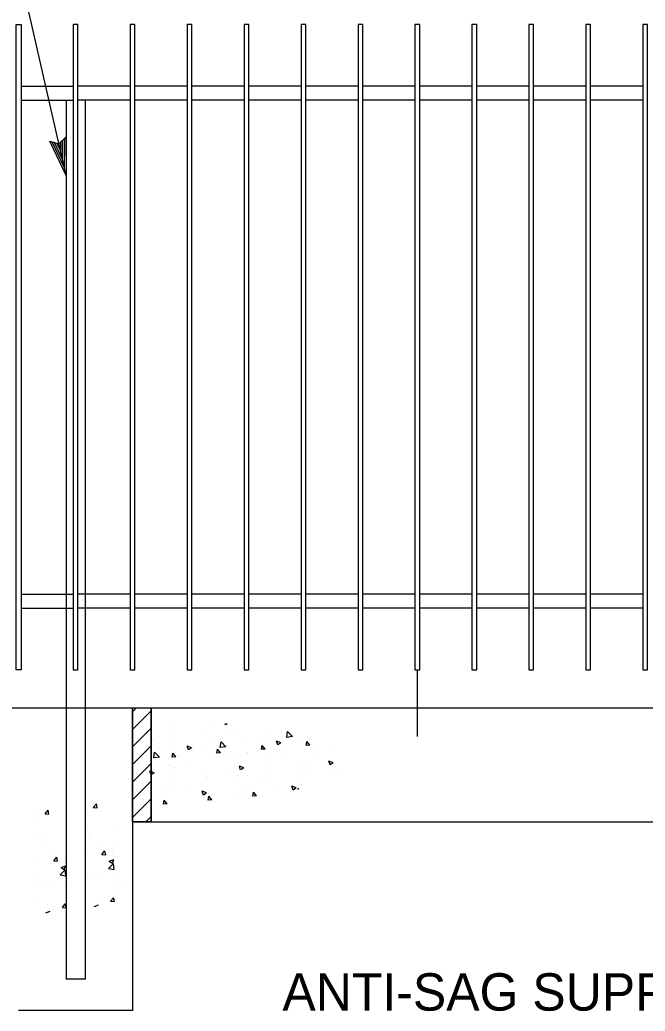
# Model space of a CAD drawing. Extents: x 6710407 to 6714861, y 1868090 to 1871317.
# Drawn here: x 6711630.5 to 6711730.9, y 1869739.6 to 1869898.7 of the extents above; entities that cross this region are included whole.
import ezdxf

# ---------------------------------------------------------------- set-up
doc = ezdxf.new("R2010")
doc.units = 0
for name, color, linetype in [('Erosion C (Lv35)', 7, 'Continuous'), ('G-MARK', 7, 'Continuous'), ('G-TEXT', 7, 'Continuous'), ('Nongeo Data(60)', 7, 'Continuous')]:
    doc.layers.add(name, color=color, linetype=linetype)

# ---------------------------------------------------------------- blocks, each defined once
blk = doc.blocks.new('SC8415')
at = {"layer": 'Erosion C (Lv35)'}
for p, q in [((-1.69662, 1.7688), (-1.69662, 1.7688)), ((-1.69606, 1.76963), (-1.69579, 1.76945)), ((-1.69579, 1.76945), (-1.69573, 1.76963)), ((-1.69408, 1.76913), (-1.69408, 1.76913)), ((-1.68715, 1.76926), (-1.68715, 1.76926)), ((-1.70943, 1.76711), (-1.70943, 1.76711)), ((-1.70689, 1.76745), (-1.70689, 1.76745)), ((-1.70669, 1.76754), (-1.7059, 1.76836)), ((-1.70669, 1.76754), (-1.70579, 1.7674)), ((-1.70579, 1.7674), (-1.7059, 1.76836)), ((-1.70304, 1.76795), (-1.70304, 1.76795)), ((-1.70278, 1.76714), (-1.70278, 1.76714)), ((-1.6975, 1.7679), (-1.6975, 1.7679)), ((-1.69309, 1.7676), (-1.69309, 1.7676)), ((-1.69228, 1.76861), (-1.69228, 1.76861)), ((-1.68716, 1.76862), (-1.68716, 1.76862)), ((-1.71312, 1.76577), (-1.71312, 1.76577)), ((-1.70955, 1.76614), (-1.70906, 1.76672)), ((-1.70955, 1.76614), (-1.70894, 1.76608)), ((-1.70894, 1.76609), (-1.70906, 1.76672)), ((-1.70791, 1.76649), (-1.70791, 1.76649)), ((-1.70672, 1.76656), (-1.70672, 1.76656)), ((-1.70494, 1.76557), (-1.70494, 1.76557)), ((-1.70484, 1.76651), (-1.70412, 1.76679)), ((-1.70484, 1.76651), (-1.70433, 1.76617)), ((-1.70433, 1.76617), (-1.70412, 1.76679)), ((-1.70226, 1.7655), (-1.70177, 1.76608)), ((-1.70226, 1.7655), (-1.70165, 1.76545)), ((-1.70165, 1.76545), (-1.70177, 1.76609)), ((-1.7013, 1.76633), (-1.7013, 1.76633)), ((-1.69901, 1.76659), (-1.69901, 1.76659)), ((-1.69588, 1.7661), (-1.69588, 1.7661)), ((-1.69585, 1.76586), (-1.69506, 1.76668)), ((-1.69585, 1.76586), (-1.69494, 1.76572)), ((-1.69494, 1.76572), (-1.69506, 1.76668)), ((-1.6929, 1.76563), (-1.6929, 1.76563)), ((-1.69045, 1.76587), (-1.69045, 1.76587)), ((-1.69023, 1.7657), (-1.68952, 1.76597)), ((-1.69023, 1.7657), (-1.68973, 1.76536)), ((-1.68973, 1.76536), (-1.68952, 1.76597)), ((-1.68727, 1.76588), (-1.68727, 1.76588)), ((-1.68649, 1.76648), (-1.68649, 1.76648)), ((-1.68503, 1.76565), (-1.68503, 1.76565)), ((-1.68473, 1.76639), (-1.68473, 1.76639)), ((-1.68394, 1.76681), (-1.68394, 1.76681)), ((-1.682, 1.76664), (-1.682, 1.76664)), ((-1.71086, 1.76455), (-1.71086, 1.76455)), ((-1.71, 1.76543), (-1.71, 1.76543)), ((-1.70571, 1.76395), (-1.70571, 1.76395)), ((-1.70458, 1.7652), (-1.70458, 1.7652)), ((-1.6993, 1.76479), (-1.6993, 1.76479)), ((-1.69916, 1.76497), (-1.69916, 1.76497)), ((-1.69762, 1.76452), (-1.69762, 1.76452)), ((-1.69675, 1.76513), (-1.69675, 1.76513)), ((-1.69658, 1.76435), (-1.69658, 1.76435)), ((-1.69497, 1.76486), (-1.69449, 1.76545)), ((-1.69497, 1.76486), (-1.69437, 1.76481)), ((-1.69437, 1.76481), (-1.69448, 1.76545)), ((-1.69373, 1.76474), (-1.69373, 1.76474)), ((-1.69241, 1.76523), (-1.69241, 1.76523)), ((-1.69065, 1.76537), (-1.69065, 1.76537)), ((-1.68831, 1.76451), (-1.68831, 1.76451)), ((-1.68769, 1.76423), (-1.6872, 1.76481)), ((-1.68769, 1.76423), (-1.68708, 1.76417)), ((-1.68708, 1.76417), (-1.6872, 1.76481)), ((-1.685, 1.76418), (-1.68421, 1.765)), ((-1.685, 1.76418), (-1.6841, 1.76404)), ((-1.6841, 1.76404), (-1.68421, 1.765)), ((-1.68289, 1.76428), (-1.68289, 1.76428)), ((-1.71337, 1.76324), (-1.71266, 1.76351)), ((-1.71337, 1.76324), (-1.71287, 1.7629)), ((-1.71325, 1.76239), (-1.71325, 1.76239)), ((-1.71287, 1.7629), (-1.71266, 1.76351)), ((-1.7121, 1.7631), (-1.7121, 1.7631)), ((-1.70956, 1.76344), (-1.70956, 1.76344)), ((-1.70843, 1.76232), (-1.70843, 1.76232)), ((-1.70803, 1.7631), (-1.70803, 1.7631)), ((-1.7029, 1.76375), (-1.7029, 1.76375)), ((-1.7025, 1.76334), (-1.7025, 1.76334)), ((-1.69877, 1.76242), (-1.69806, 1.7627)), ((-1.69877, 1.76242), (-1.69827, 1.76208)), ((-1.69826, 1.76208), (-1.69806, 1.7627)), ((-1.68916, 1.76247), (-1.68916, 1.76247)), ((-1.6874, 1.7625), (-1.6874, 1.7625)), ((-1.68662, 1.7628), (-1.68662, 1.7628)), ((-1.68277, 1.76331), (-1.68277, 1.76331)), ((-1.71417, 1.76163), (-1.71417, 1.76163)), ((-1.70874, 1.7614), (-1.70874, 1.7614)), ((-1.70332, 1.76117), (-1.70332, 1.76117)), ((-1.70197, 1.76078), (-1.70197, 1.76078)), ((-1.69943, 1.76112), (-1.69943, 1.76112)), ((-1.6979, 1.76094), (-1.6979, 1.76094)), ((-1.69775, 1.76113), (-1.69775, 1.76113)), ((-1.69558, 1.76162), (-1.69558, 1.76162)), ((-1.6927, 1.7608), (-1.6927, 1.7608)), ((-1.69253, 1.76185), (-1.69253, 1.76185)), ((-1.69247, 1.76071), (-1.69247, 1.76071)), ((-1.68677, 1.76182), (-1.68677, 1.76182)), ((-1.68417, 1.76161), (-1.68346, 1.76188)), ((-1.68417, 1.76161), (-1.68366, 1.76127)), ((-1.68366, 1.76127), (-1.68346, 1.76188)), ((-1.70839, 1.75994), (-1.70839, 1.75994)), ((-1.70815, 1.75972), (-1.70815, 1.75972)), ((-1.70775, 1.75896), (-1.70765, 1.75908)), ((-1.70762, 1.7589), (-1.70765, 1.75908)), ((-1.70731, 1.75915), (-1.7066, 1.75942)), ((-1.70731, 1.75915), (-1.7068, 1.75881)), ((-1.7068, 1.75881), (-1.7066, 1.75942)), ((-1.70302, 1.76037), (-1.70302, 1.76037)), ((-1.69862, 1.75978), (-1.69862, 1.75978)), ((-1.68752, 1.75912), (-1.68752, 1.75912)), ((-1.68705, 1.76048), (-1.68705, 1.76048)), ((-1.68544, 1.7593), (-1.68544, 1.7593)), ((-1.68224, 1.75988), (-1.68224, 1.75988)), ((-1.70455, 1.75876), (-1.70455, 1.75876)), ((-1.70085, 1.75786), (-1.70036, 1.75844)), ((-1.70085, 1.75786), (-1.70025, 1.7578)), ((-1.70024, 1.75781), (-1.70036, 1.75844)), ((-1.69825, 1.75762), (-1.69825, 1.75762)), ((-1.69787, 1.75775), (-1.69787, 1.75775)), ((-1.69357, 1.75722), (-1.69308, 1.7578)), ((-1.69296, 1.75717), (-1.69307, 1.75781)), ((-1.69271, 1.75833), (-1.692, 1.75861)), ((-1.69271, 1.75833), (-1.6922, 1.75799)), ((-1.69265, 1.75847), (-1.69265, 1.75847)), ((-1.6922, 1.75799), (-1.69199, 1.75861)), ((-1.69183, 1.75846), (-1.69183, 1.75846)), ((-1.68929, 1.7588), (-1.68929, 1.7588)), ((-1.69357, 1.75722), (-1.69296, 1.75717)), ((-1.68628, 1.75658), (-1.68579, 1.75717)), ((-1.68628, 1.75658), (-1.68567, 1.75653)), ((-1.68567, 1.75653), (-1.68579, 1.75717))]:
    blk.add_line(p, q, dxfattribs=at)

msp = doc.modelspace()

# ---------------------------------------------------------------- linework, layer by layer
at = {"layer": 'G-MARK'}
msp.add_lwpolyline([(6711637.97, 1869873.68), (6711620.12, 1869951.83), (6711630.31, 1869951.98)], dxfattribs=at)
at = {"layer": 'G-TEXT'}
for p, q in [((6711637.97, 1869873.68), (6711635.34, 1869879.23)), ((6711635.34, 1869879.23), (6711635.34, 1869879.23)), ((6711635.34, 1869879.23), (6711636.82, 1869878.75)), ((6711636.82, 1869878.75), (6711637.94, 1869879.83)), ((6711637.35, 1869879.23), (6711637.36, 1869876.37)), ((6711637.65, 1869879.54), (6711637.67, 1869875.02)), ((6711637.94, 1869879.83), (6711637.94, 1869879.83)), ((6711637.94, 1869879.83), (6711637.97, 1869873.68)), ((6711637.66, 1869875.03), (6711635.74, 1869879.08)), ((6711637.36, 1869876.37), (6711636.12, 1869878.99)), ((6711637.05, 1869877.72), (6711636.52, 1869878.84)), ((6711637.05, 1869878.98), (6711637.05, 1869877.72)), ((6711637.97, 1869873.68), (6711637.97, 1869873.68))]:
    msp.add_line(p, q, dxfattribs=at)
at = {"layer": 'Nongeo Data(60)'}
for p, q in [((6711639.5, 1869897.95), (6711639.5, 1869897.95)), ((6711630.74, 1869888.05), (6711639.12, 1869888.05)), ((6711648.26, 1869888.05), (6711639.88, 1869888.05)), ((6711657.41, 1869888.05), (6711649.02, 1869888.05)), ((6711666.55, 1869888.05), (6711658.17, 1869888.05)), ((6711675.69, 1869888.05), (6711667.31, 1869888.05)), ((6711684.84, 1869888.05), (6711676.46, 1869888.05)), ((6711693.98, 1869888.05), (6711685.6, 1869888.05)), ((6711703.13, 1869888.05), (6711694.74, 1869888.05)), ((6711712.27, 1869888.05), (6711703.89, 1869888.05)), ((6711721.41, 1869888.05), (6711713.03, 1869888.05)), ((6711730.56, 1869888.05), (6711722.18, 1869888.05)), ((6711630.74, 1869885.76), (6711639.12, 1869885.76)), ((6711637.97, 1869885.76), (6711637.97, 1869744.69)), ((6711648.26, 1869885.76), (6711639.88, 1869885.76)), ((6711641.02, 1869885.76), (6711641.02, 1869744.69)), ((6711657.41, 1869885.76), (6711649.02, 1869885.76)), ((6711666.55, 1869885.76), (6711658.17, 1869885.76)), ((6711675.69, 1869885.76), (6711667.31, 1869885.76)), ((6711684.84, 1869885.76), (6711676.46, 1869885.76)), ((6711693.98, 1869885.76), (6711685.6, 1869885.76)), ((6711703.13, 1869885.76), (6711694.74, 1869885.76)), ((6711712.27, 1869885.76), (6711703.89, 1869885.76)), ((6711721.41, 1869885.76), (6711713.03, 1869885.76)), ((6711730.56, 1869885.76), (6711722.18, 1869885.76)), ((6711630.74, 1869806.51), (6711639.12, 1869806.51)), ((6711648.26, 1869806.51), (6711639.88, 1869806.51)), ((6711657.41, 1869806.51), (6711649.02, 1869806.51)), ((6711666.55, 1869806.51), (6711658.17, 1869806.51)), ((6711675.69, 1869806.51), (6711667.31, 1869806.51)), ((6711684.84, 1869806.51), (6711676.46, 1869806.51)), ((6711693.98, 1869806.51), (6711685.6, 1869806.51)), ((6711703.13, 1869806.51), (6711694.74, 1869806.51)), ((6711712.27, 1869806.51), (6711703.89, 1869806.51)), ((6711721.41, 1869806.51), (6711713.03, 1869806.51)), ((6711730.56, 1869806.51), (6711722.18, 1869806.51)), ((6711630.74, 1869804.23), (6711639.12, 1869804.23)), ((6711648.26, 1869804.23), (6711639.88, 1869804.23)), ((6711657.41, 1869804.23), (6711649.02, 1869804.23)), ((6711666.55, 1869804.23), (6711658.17, 1869804.23)), ((6711675.69, 1869804.23), (6711667.31, 1869804.23)), ((6711684.84, 1869804.23), (6711676.46, 1869804.23)), ((6711693.98, 1869804.23), (6711685.6, 1869804.23)), ((6711703.13, 1869804.23), (6711694.74, 1869804.23)), ((6711712.27, 1869804.23), (6711703.89, 1869804.23)), ((6711721.41, 1869804.23), (6711713.03, 1869804.23)), ((6711730.56, 1869804.23), (6711722.18, 1869804.23)), ((6711694.36, 1869794.32), (6711694.36, 1869783.65)), ((6711576.51, 1869788.23), (6711904.03, 1869788.23)), ((6711630.35, 1869788.23), (6711648.64, 1869788.23)), ((6711637.97, 1869788.23), (6711641.02, 1869788.23)), ((6711648.64, 1869788.23), (6711648.64, 1869739.65)), ((6711648.64, 1869787.61), (6711649.25, 1869788.23)), ((6711648.64, 1869784.79), (6711651.64, 1869787.79)), ((6711651.64, 1869769.94), (6711651.64, 1869788.23)), ((6711648.64, 1869781.96), (6711651.64, 1869784.96)), ((6711648.64, 1869779.13), (6711651.64, 1869782.13)), ((6711648.64, 1869776.3), (6711651.64, 1869779.3)), ((6711648.64, 1869773.47), (6711651.64, 1869776.47)), ((6711642.34, 1869772.24), (6711642.83, 1869772.81)), ((6711642.94, 1869772.19), (6711642.83, 1869772.81)), ((6711648.64, 1869770.64), (6711651.64, 1869773.64)), ((6711633.7, 1869771.03), (6711633.7, 1869771.03)), ((6711634.59, 1869771.22), (6711635.08, 1869771.8)), ((6711634.59, 1869771.22), (6711635.19, 1869771.17)), ((6711635.19, 1869771.17), (6711635.08, 1869771.8)), ((6711641.45, 1869772.04), (6711641.45, 1869772.04)), ((6711642.34, 1869772.24), (6711642.94, 1869772.19)), ((6711632.97, 1869770.73), (6711632.97, 1869770.73)), ((6711646.52, 1869769.46), (6711646.52, 1869769.46)), ((6711648.64, 1869769.94), (6711813.23, 1869769.94)), ((6711650.76, 1869769.94), (6711651.64, 1869770.82)), ((6711641.33, 1869768.71), (6711641.33, 1869768.71)), ((6711641.88, 1869768.3), (6711641.88, 1869768.3)), ((6711633.58, 1869767.7), (6711633.58, 1869767.7)), ((6711633.86, 1869766.54), (6711633.86, 1869766.54)), ((6711634.13, 1869767.28), (6711634.13, 1869767.28)), ((6711641.61, 1869767.56), (6711641.61, 1869767.56)), ((6711635.58, 1869764.88), (6711635.58, 1869764.88)), ((6711641.21, 1869765.38), (6711641.21, 1869765.38)), ((6711643.32, 1869765.89), (6711643.32, 1869765.89)), ((6711643.73, 1869764.72), (6711644.21, 1869765.29)), ((6711643.73, 1869764.72), (6711644.33, 1869764.66)), ((6711644, 1869765.36), (6711644, 1869765.36)), ((6711644.33, 1869764.67), (6711644.21, 1869765.29)), ((6711645.57, 1869765.18), (6711645.57, 1869765.18)), ((6711646.4, 1869766.13), (6711646.4, 1869766.13)), ((6711633.46, 1869764.37), (6711633.46, 1869764.37)), ((6711635.98, 1869763.7), (6711636.46, 1869764.28)), ((6711635.98, 1869763.7), (6711636.58, 1869763.65)), ((6711636.25, 1869764.35), (6711636.25, 1869764.35)), ((6711636.58, 1869763.65), (6711636.46, 1869764.28)), ((6711637.68, 1869763.54), (6711637.68, 1869763.54)), ((6711637.82, 1869764.17), (6711637.82, 1869764.17)), ((6711644.78, 1869762.46), (6711645.56, 1869763.27)), ((6711644.91, 1869763.63), (6711645.61, 1869763.9)), ((6711644.91, 1869763.63), (6711645.41, 1869763.29)), ((6711645.41, 1869763.29), (6711645.62, 1869763.9)), ((6711645.43, 1869764.55), (6711645.43, 1869764.55)), ((6711645.67, 1869762.32), (6711645.56, 1869763.27)), ((6711637.03, 1869761.44), (6711637.81, 1869762.25)), ((6711637.16, 1869762.61), (6711637.86, 1869762.88)), ((6711637.16, 1869762.61), (6711637.66, 1869762.28)), ((6711637.66, 1869762.28), (6711637.87, 1869762.88)), ((6711637.92, 1869761.31), (6711637.81, 1869762.26)), ((6711641.09, 1869762.05), (6711641.09, 1869762.05)), ((6711644.78, 1869762.46), (6711645.67, 1869762.32)), ((6711645.44, 1869761.57), (6711645.44, 1869761.57)), ((6711646.28, 1869762.8), (6711646.28, 1869762.8)), ((6711633.34, 1869761.04), (6711633.34, 1869761.04)), ((6711635.19, 1869760.22), (6711635.19, 1869760.22)), ((6711637.03, 1869761.44), (6711637.92, 1869761.3)), ((6711637.69, 1869760.55), (6711637.69, 1869760.55)), ((6711641.34, 1869760.81), (6711641.34, 1869760.81)), ((6711641.99, 1869760.86), (6711641.99, 1869760.86)), ((6711642.94, 1869761.24), (6711642.94, 1869761.24)), ((6711646.67, 1869760.59), (6711646.67, 1869760.59)), ((6711633.59, 1869759.8), (6711633.59, 1869759.8)), ((6711634.24, 1869759.85), (6711634.24, 1869759.85)), ((6711640.96, 1869758.72), (6711640.96, 1869758.72)), ((6711646.16, 1869759.47), (6711646.16, 1869759.47)), ((6711633.21, 1869757.71), (6711633.21, 1869757.71)), ((6711637.37, 1869756.18), (6711637.85, 1869756.76)), ((6711637.97, 1869756.13), (6711637.85, 1869756.76)), ((6711642.81, 1869757.62), (6711642.81, 1869757.62)), ((6711645.12, 1869757.19), (6711645.6, 1869757.77)), ((6711645.12, 1869757.19), (6711645.72, 1869757.14)), ((6711645.72, 1869757.14), (6711645.6, 1869757.77)), ((6711646.6, 1869758.12), (6711646.6, 1869758.12)), ((6711634.73, 1869755.36), (6711635.43, 1869755.63)), ((6711635.06, 1869756.61), (6711635.06, 1869756.61)), ((6711637.37, 1869756.18), (6711637.97, 1869756.13)), ((6711642.48, 1869756.38), (6711643.18, 1869756.64)), ((6711641.02, 1869744.69), (6711637.97, 1869744.69)), ((6711648.64, 1869739.65), (6711630.35, 1869739.65))]:
    msp.add_line(p, q, dxfattribs=at)
for points in [[(6711630.74, 1869794.32), (6711629.97, 1869794.32), (6711629.97, 1869897.95), (6711630.74, 1869897.95)], [(6711639.12, 1869794.32), (6711639.88, 1869794.32), (6711639.88, 1869897.95), (6711639.12, 1869897.95)], [(6711648.26, 1869794.32), (6711649.02, 1869794.32), (6711649.02, 1869897.95), (6711648.26, 1869897.95)], [(6711657.41, 1869794.32), (6711658.17, 1869794.32), (6711658.17, 1869897.95), (6711657.41, 1869897.95)], [(6711666.55, 1869794.32), (6711667.31, 1869794.32), (6711667.31, 1869897.95), (6711666.55, 1869897.95)], [(6711675.69, 1869794.32), (6711676.46, 1869794.32), (6711676.46, 1869897.95), (6711675.69, 1869897.95)], [(6711684.84, 1869794.32), (6711685.6, 1869794.32), (6711685.6, 1869897.95), (6711684.84, 1869897.95)], [(6711693.98, 1869794.32), (6711694.74, 1869794.32), (6711694.74, 1869897.95), (6711693.98, 1869897.95)], [(6711703.13, 1869794.32), (6711703.89, 1869794.32), (6711703.89, 1869897.95), (6711703.13, 1869897.95)], [(6711712.27, 1869794.32), (6711713.03, 1869794.32), (6711713.03, 1869897.95), (6711712.27, 1869897.95)], [(6711721.41, 1869794.32), (6711722.18, 1869794.32), (6711722.18, 1869897.95), (6711721.41, 1869897.95)], [(6711730.56, 1869794.32), (6711731.32, 1869794.32), (6711731.32, 1869897.95), (6711730.56, 1869897.95)], [(6711648.64, 1869788.23), (6711651.64, 1869788.23), (6711651.64, 1869769.94), (6711648.64, 1869769.94)]]:
    msp.add_lwpolyline(points, close=True, dxfattribs=at)

# ---------------------------------------------------------------- block references
at = {"layer": 'Nongeo Data(60)', "xscale": 984.251968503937, "yscale": -984.251968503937, "rotation": 180}
msp.add_blockref('SC8415', (6709994.48, 1868043.94), dxfattribs=at)

# ---------------------------------------------------------------- texts
at = {"layer": 'Nongeo Data(60)'}
msp.add_text('ANTI-SAG SUPPORT FIXED', height=6, dxfattribs=at).set_placement((6711672.7, 1869739.64))

doc.saveas('drawing.dxf')
